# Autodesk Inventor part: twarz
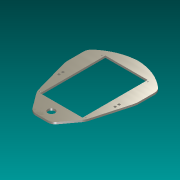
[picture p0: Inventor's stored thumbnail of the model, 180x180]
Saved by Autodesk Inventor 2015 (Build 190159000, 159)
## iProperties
Created: 2016-02
Part Number: twarz
Material: Generic
Document SubType Name: Modeling
Designer: Rafał
Density: 1 g/cm^3
Appearance: Light Beige
Author: Rafał
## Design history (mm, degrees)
sketch "Sketch1"
  geometry: L1 (0, 0)-(-107, 0); L2 (-107, 0)-(-107, 165); L3 (-107, 165)-(0, 165); L4 (0, 165)-(0, 0); L5 (-53.5, 0)-(-53.5, 165); L6 (-107, 82.5)-(0, 82.5); L7 (-53.5, 165)-(-53.5, 195); L8 (-53.5, 0)-(-53.5, -50); L9 (-53.5, 0)-(-53.5, 100); L10 (-53.5, 100)-(-143.5, 100); L11 (-53.5, 100)-(36.5, 100); L12 (-53.5, 0)-(-115.5, 0); L13 (-53.5, -50)-(-68.419, -50); L14 (-84.496, -41.897)-(-111.12, -5.918); L15 (-117.485, 7.09)-(-141.278, 92.064); L16 (-143.5, 108.242)-(-143.5, 146.423); L17 (36.5, 108.242)-(36.5, 146.423); L18 (10.485, 7.09)-(34.278, 92.064); L19 (-22.504, -41.897)-(4.12, -5.918); L20 (-53.5, -50)-(-38.581, -50); L21 (-127, 67.553)-(-122, 67.553); L22 (-122, 67.553)-(-122, 62.553); L23 (-122, 62.553)-(-127, 62.553); L24 (-127, 62.553)-(-127, 67.553); L25 (-127, 72.553)-(-122, 72.553); L26 (-122, 72.553)-(-122, 77.553); L27 (-122, 77.553)-(-127, 77.553); L28 (-127, 77.553)-(-127, 72.553); L29 (15, 72.553)-(15, 77.553); L30 (15, 77.553)-(20, 77.553); L31 (20, 77.553)-(20, 72.553); L32 (20, 72.553)-(15, 72.553); L33 (20, 67.553)-(15, 67.553); L34 (15, 67.553)-(15, 62.553); L35 (15, 62.553)-(20, 62.553); L36 (20, 62.553)-(20, 67.553); C1 r 1.5 at (4, 4); C2 r 1.5 at (-111, 4); C3 r 1.5 at (4, 161); C4 r 1.5 at (-111, 161); A1 r 134.263 centre (-47.771, 60.859) between (-53.5, 195) and (-136.755, 161.399); A2 r 20 centre (-123.5, 146.423) between (-136.755, 161.399) and (-143.5, 146.423); A3 r 20 centre (-68.419, -30) between (-84.496, -41.897) and (-68.419, -50); A4 r 40 centre (-78.967, 17.875) between (-117.485, 7.09) and (-111.12, -5.918); A5 r 60 centre (-83.5, 108.242) between (-143.5, 108.242) and (-141.278, 92.064); A6 r 134.263 centre (-59.229, 60.859) between (29.755, 161.399) and (-53.5, 195); A7 r 20 centre (16.5, 146.423) between (36.5, 146.423) and (29.755, 161.399); A8 r 60 centre (-23.5, 108.242) between (34.278, 92.064) and (36.5, 108.242); A9 r 40 centre (-28.033, 17.875) between (4.12, -5.918) and (10.485, 7.09); A10 r 20 centre (-38.581, -30) between (-38.581, -50) and (-22.504, -41.897); 2 further points
  constraints: 72 end point, 24 symmetric about line, 21 point on circle, 14 centre point, 9 point on line, 8 tangent, 7 perpendicular, 6 parallel, 4 horizontal, 4 midpoint, 1 vertical, 8 other
  dimensions: "d0" = 107 distance of L2.end L3.end; "d1" = 165 distance of L1.end L2.end; "d2" = 3 diameter of C1; "d3" = 4 distance from line of L4 C1.centre; "d4" = 4 distance from line of L1 C1.centre; "d5" = 30 distance of L5.end L7.end; "d6" = 50 distance of L5.start L8.end; "d7" = 100 distance of L5.start L9.end; "d8" = 90 distance of L9.end L10.end; "d9" = 90 distance of L9.end L11.end; "d10" = 62 distance of L5.start L12.end; "d11" = 25 distance of L8.end point (-78.5, -50); "d12" = 55 distance of L10.end point (-143.5, 155); "d13" = 20 radius of A2; "d14" = 20 radius of A3; "d15" = 40 radius of A4; "d16" = 60 radius of A5; "d19" = 5 distance of L22.end L23.end; "d20" = 5 distance of L21.end L22.end; "d21" = 15 distance between parallel lines of L2 L22; "d22" = 5 distance of L26.end L25.end; "d23" = 5 distance between parallel lines of L21 L25
extrude "Extrusion2" new body sketch "Sketch1" distance "d24" = 5; taper "d25" = 0 deg
sketch "Sketch2"
  geometry: L1 (0, 0)-(-107, 0) reference; L2 (-53.5, 0)-(-53.5, -50.11); C1 r 9 at (-53.5, -25.055)
  constraints: 2 end point, 2 midpoint, 1 centre point, 1 vertical
  dimensions: "d26" = 18 diameter of C1
extrude "Extrusion3" cut sketch "Sketch2" distance "d27" = 10; taper "d28" = 0 deg
body "Solid2"
